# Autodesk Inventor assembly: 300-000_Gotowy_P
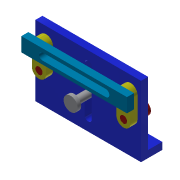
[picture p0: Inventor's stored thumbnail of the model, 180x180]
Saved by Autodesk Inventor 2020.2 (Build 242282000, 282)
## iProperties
Created: 2014-01
Part Number: 300-000_Gotowy_P
Document SubType Name: Assembly
Designer: F.Stasiak
Manager: www.cadconsulting.pl
Company: Fabian Stasiak CAD Consulting
Author: F.Stasiak
Subject: Zbiór ćwiczeń. Autodesk Inventor 2020. Kurs podstawowy
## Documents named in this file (6)
- C:\2020_Kurs_podstawowy\R6 Zespoły\Warsztat\Gotowe\300-000_Gotowy_P.iam
- C:\2020_Kurs_podstawowy\R6 Zespoły\Warsztat\Komponenty\300-001.ipt
- C:\2020_Kurs_podstawowy\R6 Zespoły\Warsztat\Komponenty\300-002.ipt
- C:\2020_Kurs_podstawowy\R6 Zespoły\Warsztat\Komponenty\300-003.ipt
- C:\2020_Kurs_podstawowy\R6 Zespoły\Warsztat\Komponenty\300-004.ipt
- C:\2020_Kurs_podstawowy\R6 Zespoły\Warsztat\Komponenty\300-005.ipt
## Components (7 placed, 5 different names)
1. 300-001:1 — Wstaw:1, Wstaw:2, Kąt:1, Wstaw:5, Wstaw:6
2. 300-002:1 — NAPĘD, Wstaw:1, Wstaw:3
3. 300-002:2 — Wstaw:2, Wstaw:4
4. 300-003:1 — Wstaw:3, Wstaw:4, Kąt:1, Zestawiający:1
5. 300-004:1 — Wstaw:6
6. 300-004:2 — Wstaw:5
7. 300-005:1 — Zestawiający:1
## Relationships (9: Insert 6, Angle 2, Mate 1)
- NAPĘD [Angle]: 300-002:1
- Wstaw:1 [Insert]: 300-001:1 ↔ 300-002:1
- Wstaw:2 [Insert]: 300-001:1 ↔ 300-002:2
- Wstaw:3 [Insert]: 300-002:1 ↔ 300-003:1
- Wstaw:4 [Insert]: 300-002:2 ↔ 300-003:1
- Kąt:1 [Angle]: 300-001:1 ↔ 300-003:1
- Wstaw:5 [Insert]: 300-001:1 ↔ 300-004:2
- Wstaw:6 [Insert]: 300-001:1 ↔ 300-004:1
- Zestawiający:1 [Mate]: 300-003:1 ↔ 300-005:1
